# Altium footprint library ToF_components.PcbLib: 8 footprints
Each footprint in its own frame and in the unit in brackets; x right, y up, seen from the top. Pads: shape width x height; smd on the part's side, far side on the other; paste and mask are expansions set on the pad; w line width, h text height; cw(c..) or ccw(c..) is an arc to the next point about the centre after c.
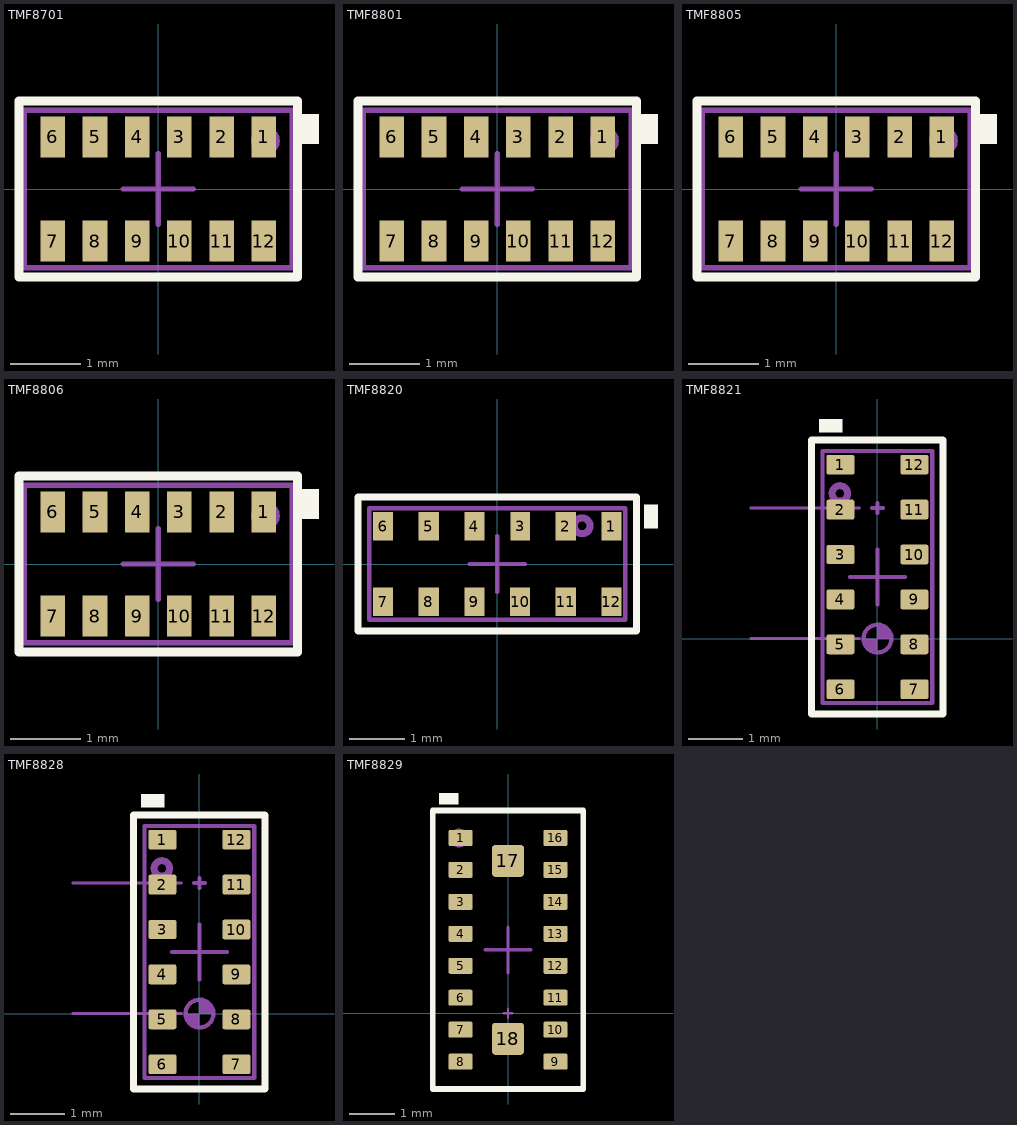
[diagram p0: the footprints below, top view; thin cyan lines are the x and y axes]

## TMF8701 [mm] "TMF8701"
height 0.74
pads (12):
  rect 0.35x0.58 smd mask+0.075: 1(1.5,0.74) 2(0.9,0.74) 3(0.3,0.74) 4(-0.3,0.74) 5(-0.9,0.74) 6(-1.5,0.74) 7(-1.5,-0.74) 8(-0.9,-0.74) 9(-0.3,-0.74) 10(0.3,-0.74) 11(0.9,-0.74) 12(1.5,-0.74)
Top Overlay:
  rectangle: 2.036,0.642 2.286,1.067
  lines w0.127: -1.981,-1.25 1.981,-1.25 1.981,1.25 -1.981,1.25 -1.981,-1.25
Mechanical 1:
  lines w0.075: -0.5,0 0.5,0 ; 0,-0.5 0,0.5
Top Assembly:
  circle w0.127: c1.524,0.686 r0.141
  lines w0.076: -1.905,-1.118 -1.905,1.118 1.905,1.118 1.905,-1.118 -1.905,-1.118
  text "'.Designator'" at -1.8,-0.2 h0.75
3D body "TMF8701_2017-12-04.STEP": height 1, standoff 0, extent -1.799,-1.1 1.803,1.1

## TMF8801 [mm] "TMF8801"
height 0.74
pads (12):
  rect 0.35x0.58 smd mask+0.075: 1(1.5,0.74) 2(0.9,0.74) 3(0.3,0.74) 4(-0.3,0.74) 5(-0.9,0.74) 6(-1.5,0.74) 7(-1.5,-0.74) 8(-0.9,-0.74) 9(-0.3,-0.74) 10(0.3,-0.74) 11(0.9,-0.74) 12(1.5,-0.74)
Top Overlay:
  rectangle: 2.036,0.642 2.286,1.067
  lines w0.127: -1.981,-1.25 -1.981,1.25 1.981,1.25 1.981,-1.25 -1.981,-1.25
Mechanical 1:
  lines w0.075: -0.5,0 0.5,0 ; 0,-0.5 0,0.5
Top Assembly:
  circle w0.127: c1.524,0.686 r0.141
  lines w0.076: -1.905,-1.118 1.905,-1.118 1.905,1.118 -1.905,1.118 -1.905,-1.118
  text "'.Designator'" at -1.8,-0.2 h0.75
3D body "TMF8701_2017-12-04.STEP": height 1, standoff 0, extent -1.799,-1.1 1.803,1.1

## TMF8805 [mm] "TMF8805"
height 0.74
pads (12):
  rect 0.35x0.58 smd mask+0.075: 1(1.5,0.74) 2(0.9,0.74) 3(0.3,0.74) 4(-0.3,0.74) 5(-0.9,0.74) 6(-1.5,0.74) 7(-1.5,-0.74) 8(-0.9,-0.74) 9(-0.3,-0.74) 10(0.3,-0.74) 11(0.9,-0.74) 12(1.5,-0.74)
Top Overlay:
  rectangle: 2.036,0.642 2.286,1.067
  lines w0.127: -1.981,-1.25 1.981,-1.25 1.981,1.25 -1.981,1.25 -1.981,-1.25
Mechanical 1:
  lines w0.075: -0.5,0 0.5,0 ; 0,-0.5 0,0.5
Top Assembly:
  circle w0.127: c1.524,0.686 r0.141
  lines w0.076: -1.905,-1.118 -1.905,1.118 1.905,1.118 1.905,-1.118 -1.905,-1.118
  text "'.Designator'" at -1.8,-0.2 h0.75
3D body "TMF8701_2017-12-04.STEP": height 1, standoff 0, extent -1.799,-1.1 1.803,1.1

## TMF8806 [mm] "TMF8806"
height 0.74
pads (12):
  rect 0.35x0.58 smd mask+0.075: 1(1.5,0.74) 2(0.9,0.74) 3(0.3,0.74) 4(-0.3,0.74) 5(-0.9,0.74) 6(-1.5,0.74) 7(-1.5,-0.74) 8(-0.9,-0.74) 9(-0.3,-0.74) 10(0.3,-0.74) 11(0.9,-0.74) 12(1.5,-0.74)
Top Overlay:
  rectangle: 2.036,0.642 2.286,1.067
  lines w0.127: -1.981,-1.25 -1.981,1.25 1.981,1.25 1.981,-1.25 -1.981,-1.25
Mechanical 1:
  lines w0.075: -0.5,0 0.5,0 ; 0,-0.5 0,0.5
Top Assembly:
  circle w0.127: c1.524,0.686 r0.141
  lines w0.076: -1.905,-1.118 1.905,-1.118 1.905,1.118 -1.905,1.118 -1.905,-1.118
  text "'.Designator'" at -1.8,-0.2 h0.75
3D body "TMF8701_2017-12-04.STEP": height 1, standoff 0, extent -1.799,-1.1 1.803,1.1

## TMF8820 [mm] "TMF8820"
height 0.74
pads (12):
  rect 0.36x0.51 smd: 1(2.05,0.675) 2(1.23,0.675) 4(-0.41,0.675) 5(-1.23,0.675) 6(-2.05,0.675) 7(-2.05,-0.675) 8(-1.23,-0.675) 9(-0.41,-0.675) 10(0.41,-0.675) 11(1.23,-0.675) 12(2.05,-0.675)
  rect 0.35x0.51 smd: 3(0.41,0.675)
Top Overlay:
  rectangle: 2.636,0.642 2.886,1.067
  lines w0.127: -2.5,-1.2 -2.5,1.2 2.5,1.2 2.5,-1.2 -2.5,-1.2
Mechanical 1:
  lines w0.075: -0.5,0 0.5,0 ; 0,-0.5 0,0.5
Top Assembly:
  circle w0.127: c1.524,0.686 r0.141
  lines w0.076: -2.3,-1 2.3,-1 2.3,1 -2.3,1 -2.3,-1
  text "'.Designator'" at -1.8,-0.2 h0.75
3D body "Bedwell_V14.STEP": height 1.2, standoff -0.2, extent -2.3,-1 2.3,1

## TMF8821 [mm]
height 0.8
pads (12):
  rrect20% 0.51x0.36 smd mask+0.05: 1(-0.675,3.175) 2(-0.675,2.355) 4(-0.675,0.715) 5(-0.675,-0.105) 6(-0.675,-0.925) 7(0.675,-0.925) 8(0.675,-0.105) 9(0.675,0.715) 10(0.675,1.535) 11(0.675,2.355) 12(0.675,3.175)
  rrect20% 0.51x0.35 smd mask+0.05: 3(-0.675,1.535)
Top Overlay:
  region: -0.642,3.761 -0.642,4.011 -1.067,4.011 -1.067,3.761
  lines w0.127: -1.2,-1.375 1.2,-1.375 1.2,3.625 -1.2,3.625 -1.2,-1.375
Mechanical 2:
  region: 0,-0.268 -0.053,-0.268 -0.152,-0.227 -0.227,-0.152 -0.268,-0.054 -0.268,0 0,0
  region: 0,0.291 0.058,0.291 0.165,0.247 0.247,0.165 0.291,0.058 0.291,0 0,0
  lines w0.051: -2.311,0.002 -0.327,0 ; -2.311,2.385 -0.327,2.383
  lines w0.076: -0.102,2.383 0.102,2.383 ; 0,2.291 0,2.469 ; 0.254,0 cw(c0,0) 0.254,0.009
  text "VCSEL" at -4.834,2.131 h0.51
  text "SPAD" at -4.326,-0.252 h0.51
Board:
  lines w0.075: -0.5,1.125 0.5,1.125 ; 0,0.625 0,1.625
Top Assembly:
  circle w0.127: c-0.686,2.649 r0.141
  lines w0.076: -1,-1.175 1,-1.175 1,3.425 -1,3.425 -1,-1.175
3D body "TMF8828_FoI_FoV_PD001050_1-00.STEP": height 1.45, standoff 0.05, extent -1,-1.175 1,3.425

## TMF8828 [mm] "Optical Sensor 0.394\" ~ 196.85\" (10mm ~ 5000mm) Push-Pull Output"
height 0.8
pads (12):
  rrect20% 0.51x0.36 smd mask+0.05: 1(-0.675,3.175) 2(-0.675,2.355) 4(-0.675,0.715) 5(-0.675,-0.105) 6(-0.675,-0.925) 7(0.675,-0.925) 8(0.675,-0.105) 9(0.675,0.715) 10(0.675,1.535) 11(0.675,2.355) 12(0.675,3.175)
  rrect20% 0.51x0.35 smd mask+0.05: 3(-0.675,1.535)
Top Overlay:
  region: -0.642,3.761 -0.642,4.011 -1.067,4.011 -1.067,3.761
  lines w0.127: -1.2,-1.375 1.2,-1.375 1.2,3.625 -1.2,3.625 -1.2,-1.375
Mechanical 2:
  region: 0,-0.268 -0.053,-0.268 -0.152,-0.227 -0.227,-0.152 -0.268,-0.054 -0.268,0 0,0
  region: 0,0.291 0.058,0.291 0.165,0.247 0.247,0.165 0.291,0.058 0.291,0 0,0
  lines w0.051: -2.311,0.002 -0.327,0 ; -2.311,2.385 -0.327,2.383
  lines w0.076: -0.102,2.383 0.102,2.383 ; 0,2.291 0,2.469 ; 0.254,0 cw(c0,0) 0.254,0.009
  text "VCSEL" at -4.834,2.131 h0.51
  text "SPAD" at -4.326,-0.252 h0.51
Board:
  lines w0.075: -0.5,1.125 0.5,1.125 ; 0,0.625 0,1.625
Top Assembly:
  circle w0.127: c-0.686,2.649 r0.141
  lines w0.076: -1,-1.175 1,-1.175 1,3.425 -1,3.425 -1,-1.175
3D body "TMF8828_FoI_FoV_PD001050_1-00.STEP": height 1.45, standoff 0.05, extent -1,-1.175 1,3.425

## TMF8829 [mm] "TMF8829"
height 1.5
pads (18):
  rrect20% 0.53x0.35 smd mask+0.05: 1(-1.04,3.842) 2(-1.04,3.142) 3(-1.04,2.442) 4(-1.04,1.742) 5(-1.04,1.042) 6(-1.04,0.342) 7(-1.04,-0.358) 8(-1.04,-1.058) 9(1.04,-1.058) 10(1.04,-0.358) 11(1.04,0.342) 12(1.04,1.042) 13(1.04,1.742) 14(1.04,2.442) 15(1.04,3.142) 16(1.04,3.842)
  rrect20% 0.7x0.7 smd mask+0.05: 17(0,3.342) 18(0,-0.558)
Top Overlay:
  region: -1.089,4.578 -1.089,4.828 -1.514,4.828 -1.514,4.578
  lines w0.127: -1.65,-1.658 1.65,-1.658 1.65,4.442 -1.65,4.442 -1.65,-1.658
Mechanical 2:
  lines w0.051: -0.1,0 0.1,0 ; -0.1,3.137 0.1,3.137 ; 0,-0.1 0,0.1 ; 0,3.037 0,3.237
  text "Photodiodes" at 0.427,-0.304 h0.51
  text "Emitters" at 0.377,2.883 h0.51
Top Assembly:
  circle w0.127: c-1.075,3.842 r0.141
  lines w0.075: -0.5,1.392 0.5,1.392 ; 0,0.892 0,1.892
3D body "TD-A00130_04_PJ540065_Fresnel_P1_A.STEP": height 1.51, standoff 0.01, extent -1.45,-1.458 1.45,4.242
